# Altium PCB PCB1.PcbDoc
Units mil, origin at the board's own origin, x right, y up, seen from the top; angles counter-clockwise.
Board outline 4318 x 4350 mil, 2 copper layers (Top Layer, Bottom Layer); 0 components, 46 nets, 149 pads, 0 vias.
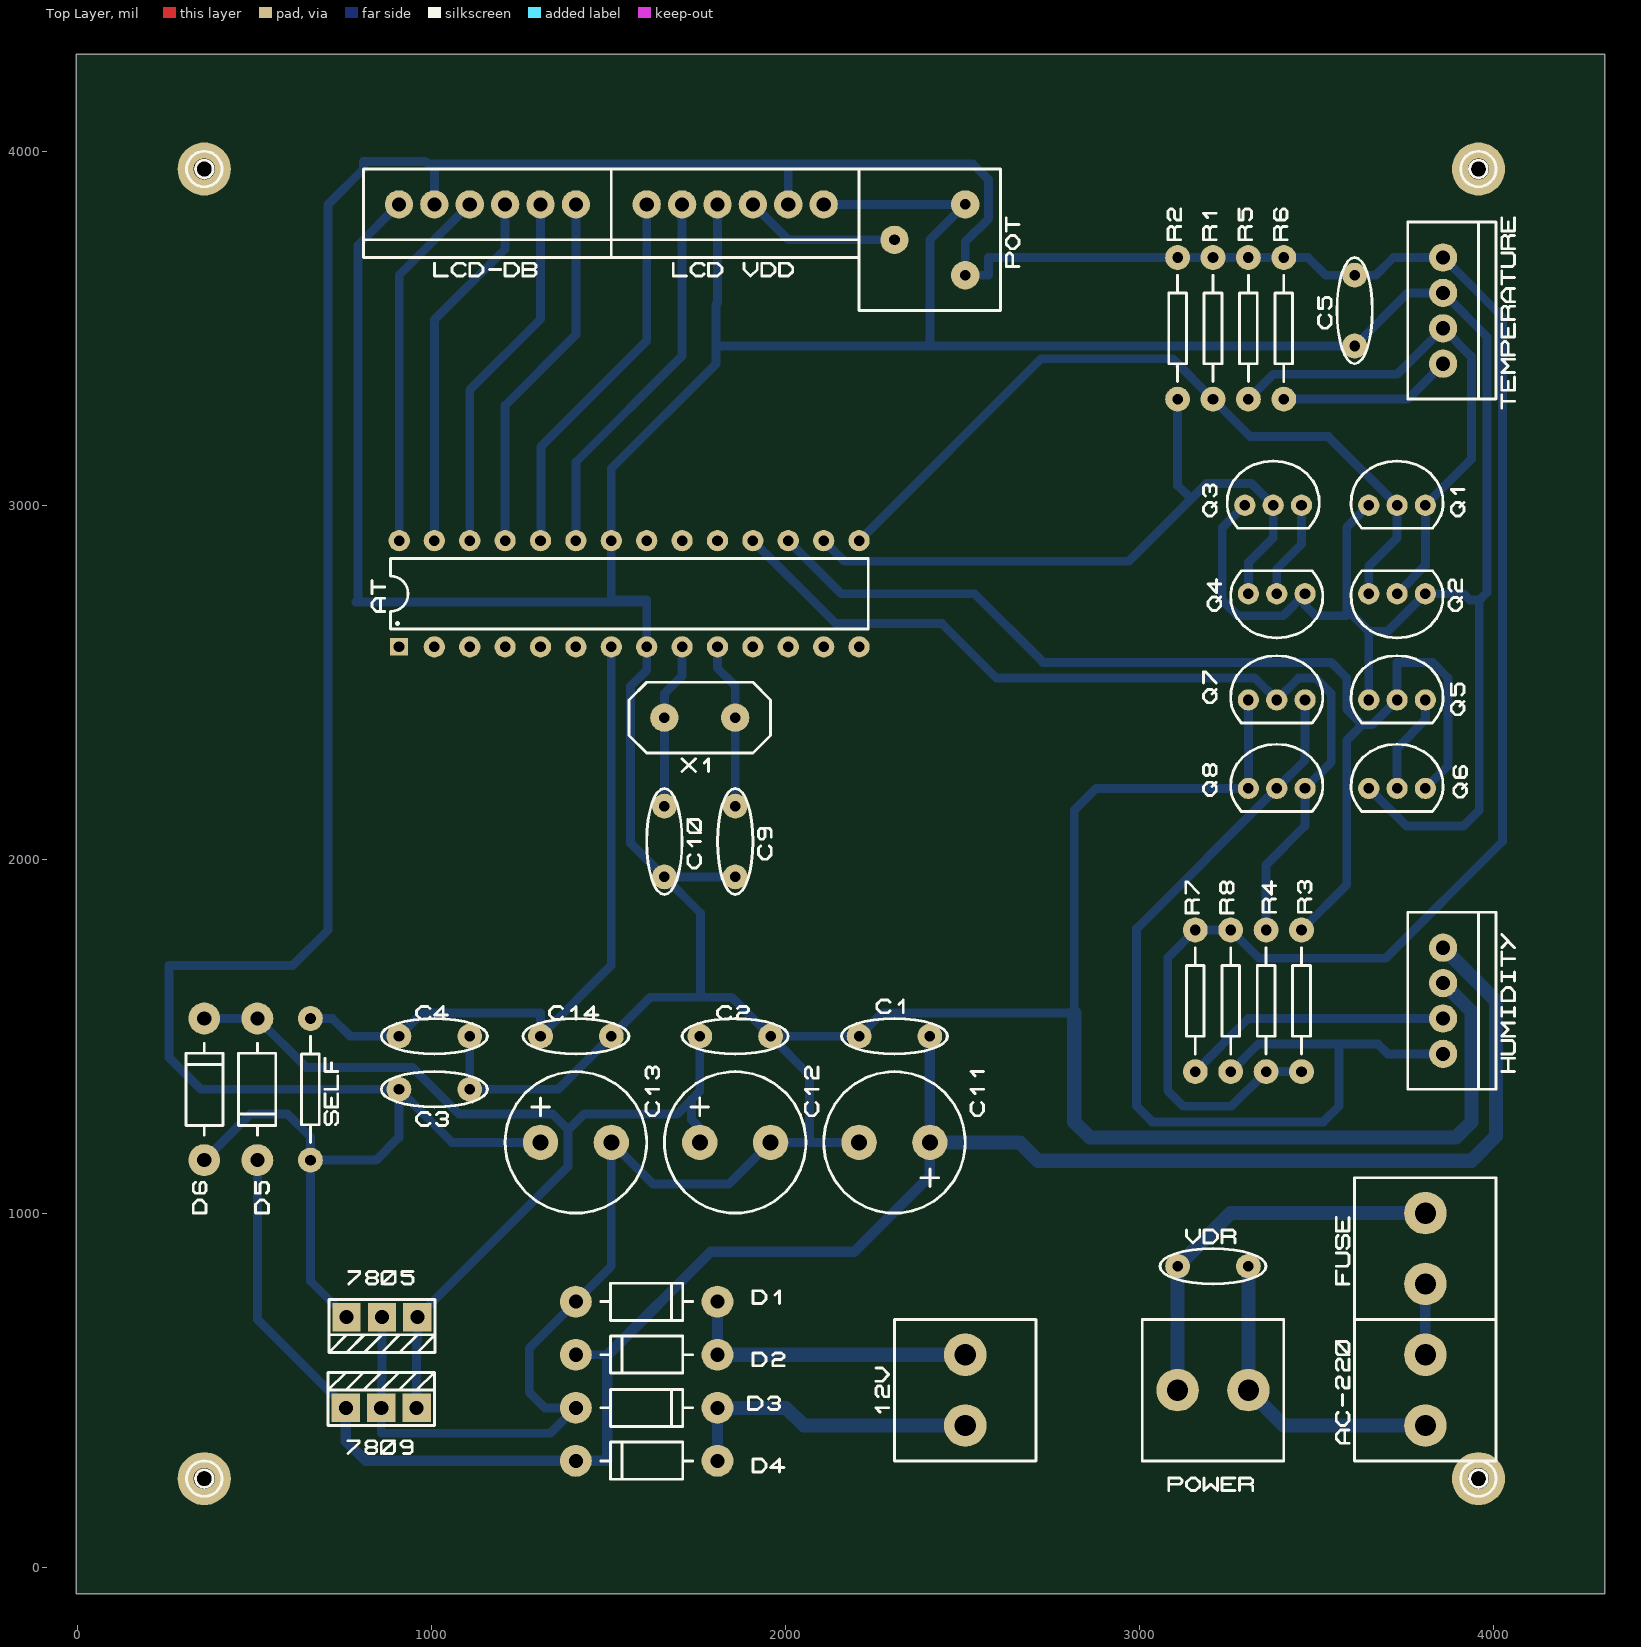
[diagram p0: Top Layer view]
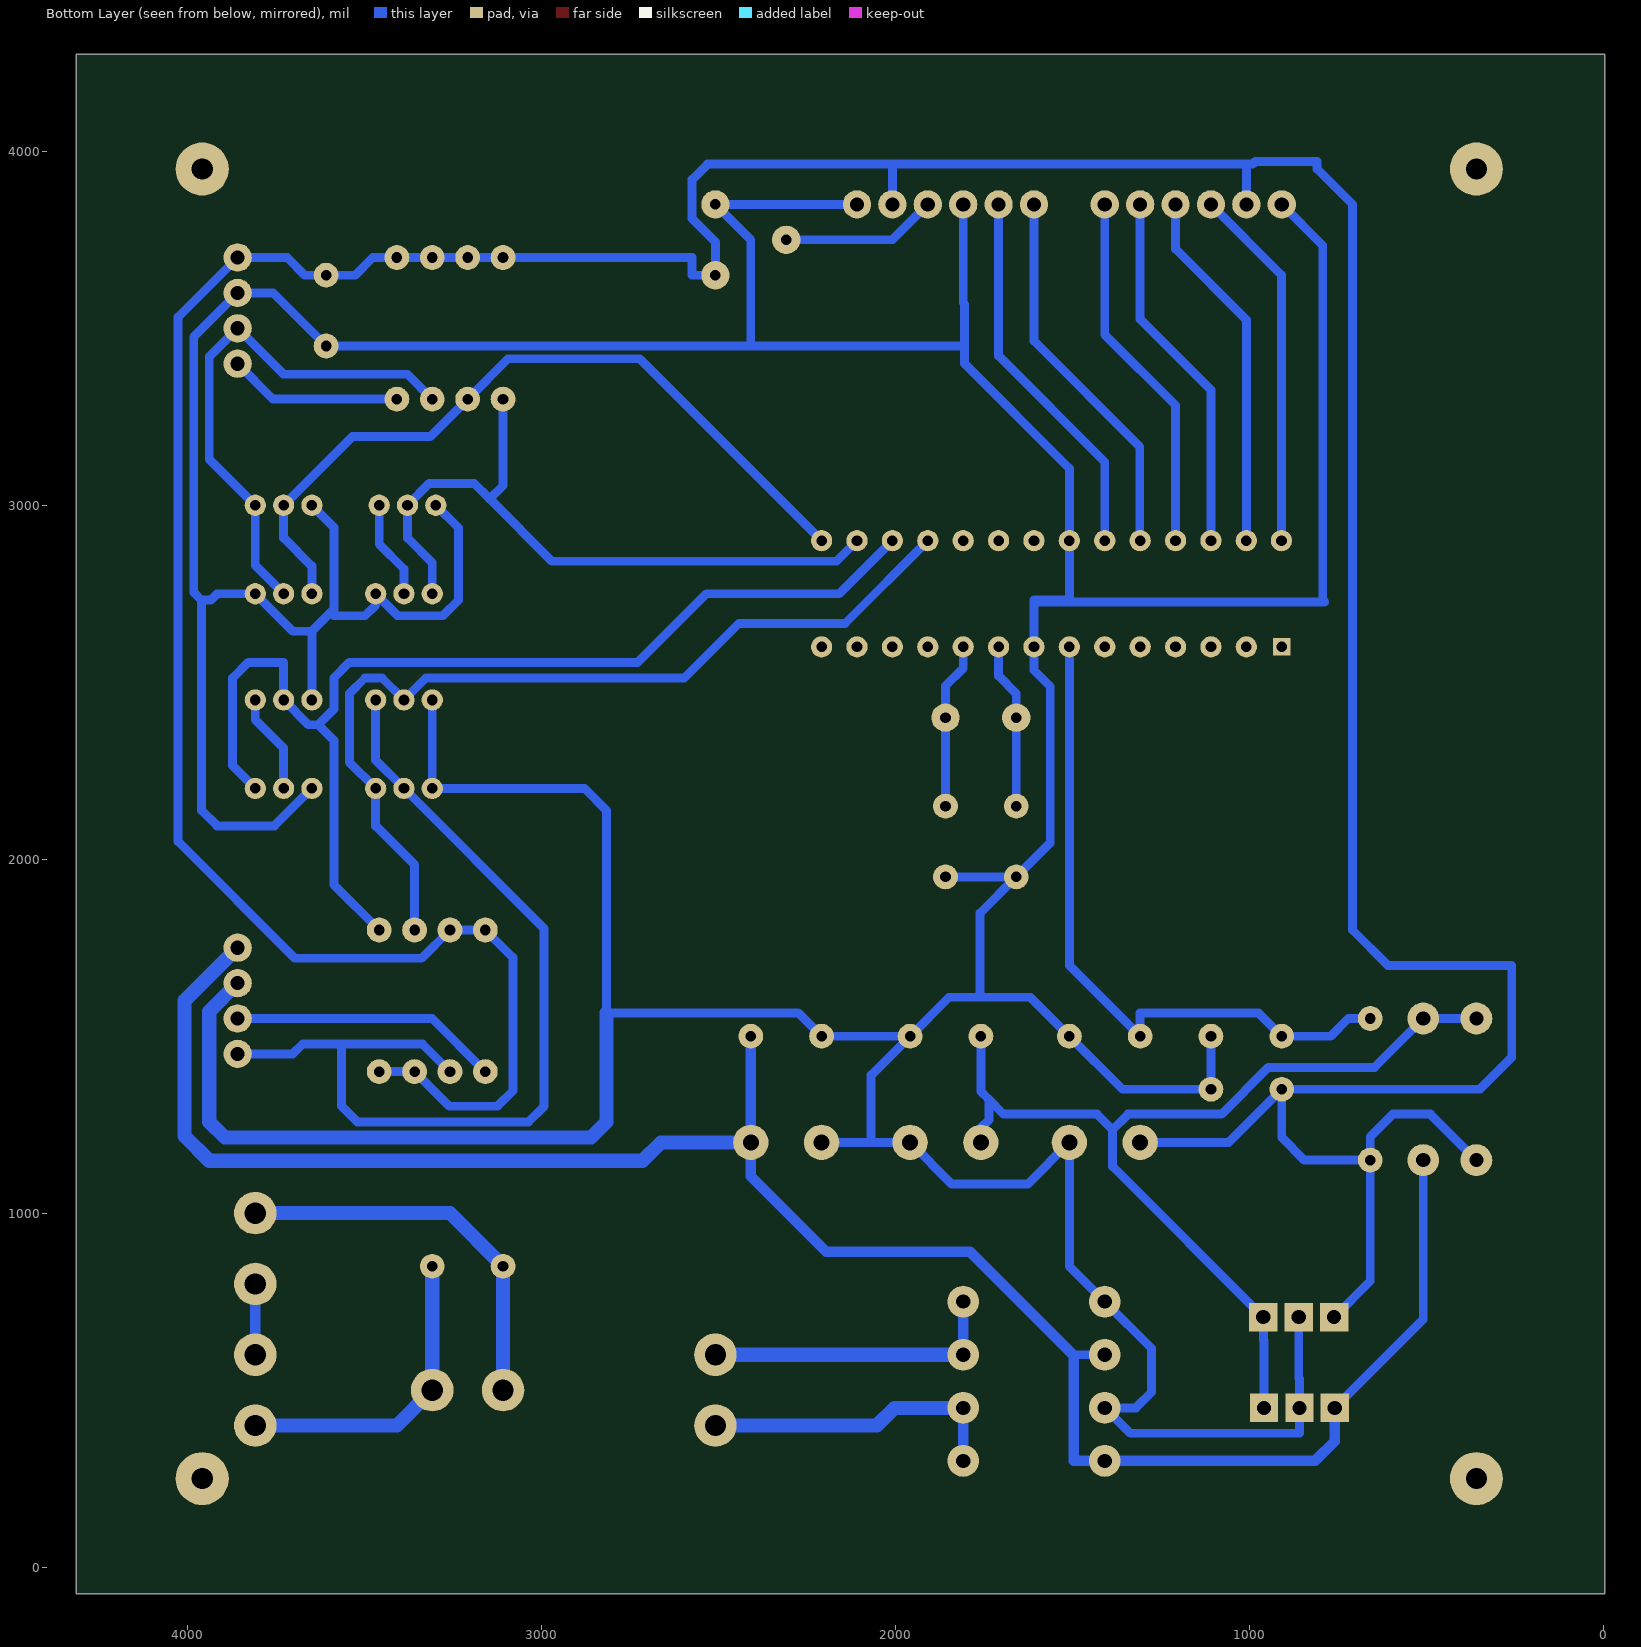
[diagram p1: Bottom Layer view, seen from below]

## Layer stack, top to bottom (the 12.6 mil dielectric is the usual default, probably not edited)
Top Layer: signal copper 1.4
Dielectric: dielectric 12.6, FR-4, Dk 4.8
Bottom Layer: signal copper 1.4

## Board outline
-4,-75 4314,-75 4314,4275 -4,4275

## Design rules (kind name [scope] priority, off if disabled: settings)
Clearance CAM_Clearance_2 [OnLayer('Top Layer')] p1: gap=10
Clearance CAM_Clearance_1 [OnLayer('Bottom Layer')] p2: gap=0
Clearance [All] p3: gap=10
PolygonConnect [All] p1: connectstyle=Relief reliefconductorwidth=10 reliefentries=4 polygonreliefangle="90 Angle"
RoutingVias [All] p1: holewidth=28 width=50 viastyle="Through Hole" minholewidth=28 minwidth=50 maxholewidth=28 maxwidth=50
SilkscreenOverComponentPads [All] p1: minsilkscreentomaskgap=10
SolderMaskExpansion [All] p1: expansion=4
Width CAM_Width_1 [OnLayer('Bottom Layer')] p1: maxlimit=41 minlimit=24 preferedwidth=25
Width [All] p2: maxlimit=10 minlimit=10 preferedwidth=10
27 further rules are at their usual default settings.

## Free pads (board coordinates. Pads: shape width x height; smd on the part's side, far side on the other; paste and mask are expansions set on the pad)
  round 150 hole 60: 1(357.92,250.5) 1(357.92,3950.49) 1(3957.92,250.5) 1(3957.92,3950.49)
  round 90 hole 40: 1(357.92,1150.49) 1(357.92,1550.49) 1(507.92,1150.49) 1(507.92,1550.49) 1(1407.92,300.5) 1(1407.92,450.5) 1(1407.92,600.5) 1(1407.92,750.5) 1(1807.92,300.5) 1(1807.92,450.5) 1(1807.92,600.5) 1(1807.92,750.5)
  round 70 hole 30: 1(657.92,1150.49) 1(657.92,1550.49) 1(907.92,1350.49) 1(907.92,1500.49) 1(1107.92,1350.49) 1(1107.92,1500.49) 1(1307.92,1500.49) 1(1507.92,1500.49) 1(1657.92,1950.49) 1(1657.92,2150.49) 1(1757.92,1500.49) 1(1857.92,1950.49) 1(1857.92,2150.49) 1(1957.92,1500.49) 1(2207.92,1500.49) 1(2407.92,1500.49) 1(3107.92,850.5) 1(3107.92,3300.49) 1(3107.92,3700.49) 1(3157.92,1400.49) 1(3157.92,1800.49) 1(3207.92,3300.49) 1(3207.92,3700.49) 1(3257.92,1400.49) 1(3257.92,1800.49) 1(3307.92,850.5) 1(3307.92,3300.49) 1(3307.92,3700.49) 1(3357.92,1400.49) 1(3357.92,1800.49) 1(3407.92,3300.49) 1(3407.92,3700.49) 1(3457.92,1400.49) 1(3457.92,1800.49) 1(3607.92,3450.49) 1(3607.92,3650.49)
  rect 80x80 hole 40: 1(757.92,450.5) 1(759.92,706.79) 1(857.92,450.5) 1(859.92,706.79) 1(957.92,450.5) 1(959.92,706.79)
  rect 50x50 hole 30: 1(907.92,2600.49)
  round 80 hole 40: 1(907.92,3850.49) 1(1007.92,3850.49) 1(1107.92,3850.49) 1(1207.92,3850.49) 1(1307.92,3850.49) 1(1407.92,3850.49) 1(1607.92,3850.49) 1(1707.92,3850.49) 1(1807.92,3850.49) 1(1907.92,3850.49) 1(2007.92,3850.49) 1(2107.92,3850.49) 1(3857.92,1450.49) 1(3857.92,1550.49) 1(3857.92,1650.49) 1(3857.92,1750.49) 1(3857.92,3400.49) 1(3857.92,3500.49) 1(3857.92,3600.49) 1(3857.92,3700.49)
  round 60 hole 30: 1(908.72,2900.49) 1(1007.92,2600.49) 1(1007.92,2900.49) 1(1107.92,2600.49) 1(1107.92,2900.49) 1(1207.92,2600.49) 1(1207.92,2900.49) 1(1307.92,2600.49) 1(1307.92,2900.49) 1(1407.92,2600.49) 1(1407.92,2900.49) 1(1507.92,2600.49) 1(1507.92,2900.49) 1(1607.92,2600.49) 1(1607.92,2900.49) 1(1707.92,2600.49) 1(1707.92,2900.49) 1(1807.92,2600.49) 1(1807.92,2900.49) 1(1907.92,2600.49) 1(1907.92,2900.49) 1(2007.92,2600.49) 1(2007.92,2900.49) 1(2107.92,2600.49) 1(2107.92,2900.49) 1(2207.92,2600.49) 1(2207.92,2900.49) 1(3297.92,3000.49) 1(3307.92,2200.49) 1(3307.92,2450.49) 1(3307.92,2750.49) 1(3377.92,3000.49) 1(3387.92,2200.49) 1(3387.92,2450.49) 1(3387.92,2750.49) 1(3457.92,3000.49) 1(3467.92,2200.49) 1(3467.92,2450.49) 1(3467.92,2750.49) 1(3647.92,2200.49) 1(3647.92,2450.49) 1(3647.92,2750.49) 1(3647.92,3000.49) 1(3727.92,2200.49) 1(3727.92,2450.49) 1(3727.92,2750.49) 1(3727.92,3000.49) 1(3807.92,2200.49) 1(3807.92,2450.49) 1(3807.92,2750.49) 1(3807.92,3000.49)
  round 100 hole 45: 1(1307.92,1200.49) 1(1507.92,1200.49) 1(1757.92,1200.49) 1(1957.92,1200.49) 1(2207.92,1200.49) 1(2407.92,1200.49)
  round 80 hole 30: 1(1657.92,2400.49) 1(1857.92,2400.49) 1(2307.92,3750.49) 1(2507.92,3650.49) 1(2507.92,3850.49)
  round 120 hole 60: 1(2507.92,400.5) 1(2507.92,600.5) 1(3107.92,500.5) 1(3307.92,500.5) 1(3807.92,400.5) 1(3807.92,600.5) 1(3807.92,800.5) 1(3807.92,1000.5)

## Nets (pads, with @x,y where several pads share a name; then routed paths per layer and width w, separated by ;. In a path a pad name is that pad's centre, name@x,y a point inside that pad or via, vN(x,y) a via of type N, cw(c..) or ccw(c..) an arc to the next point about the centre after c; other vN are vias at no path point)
$Net0: pad.1@907.92,2600.49
$Net1: pad.1@1007.92,2600.49
$Net2: pad.1@1107.92,2600.49
$Net3: pad.1@1207.92,2600.49
$Net4: pad.1@1307.92,2600.49
$Net5: pad.1@1407.92,2600.49
$Net6: pad.1@657.92,1550.49 pad.1@907.92,1500.49 pad.1@1307.92,1500.49 pad.1@1507.92,2600.49 | length 1946.9
  Bottom Layer w25: pad.1@657.92,1550.49 719.92,1550.49 769.92,1500.49 907.92,1500.49 973.92,1566.49 1307.92,1566.49 1307.92,1500.49 1507.92,1700.49 pad.1@1507.92,2600.49
$Net7: pad.1@857.92,450.5 pad.1@859.92,706.79 pad.1@907.92,3850.49 pad.1@1107.92,1350.49 pad.1@1107.92,1500.49 pad.1@1407.92,450.5 pad.1@1407.92,750.5 pad.1@1507.92,1200.49 pad.1@1507.92,1500.49 pad.1@1507.92,2900.49 pad.1@1607.92,2600.49 pad.1@1657.92,1950.49 pad.1@1807.92,3850.49 pad.1@1857.92,1950.49 pad.1@1957.92,1200.49 pad.1@1957.92,1500.49 pad.1@2107.92,3850.49 pad.1@2207.92,1200.49 pad.1@2207.92,1500.49 pad.1@2507.92,3850.49 pad.1@3297.92,3000.49 pad.1@3307.92,2200.49 pad.1@3307.92,2450.49 pad.1@3467.92,2750.49 pad.1@3607.92,3450.49 pad.1@3647.92,2200.49 pad.1@3647.92,2450.49 pad.1@3647.92,3000.49 pad.1@3807.92,2750.49 pad.1@3857.92,1650.49 pad.1@3857.92,3600.49 | length 19607.3
  Bottom Layer w25: pad.1@859.92,706.79 859.92,534.5 857.92,532.5 857.92,450.5 857.92,378.5 1335.92,378.5 1407.92,450.5 1319.92,450.5 1275.92,494.5 1275.92,618.5 1407.92,750.5 1507.92,850.5 1507.92,1200.49 1625.92,1082.49 1839.92,1082.49 1957.92,1200.49 2067.92,1200.49 ; pad.1@907.92,3850.49 791.92,3734.49 791.92,2842.49 791.92,2732.7 787.02,2727.7 1603.22,2727.7 1607.92,2732.49 ; pad.1@1107.92,1500.49 1107.92,1350.49 1357.92,1350.49 1507.92,1500.49 1617.92,1610.49 1759.92,1610.49 ; pad.1@1807.92,3850.49 1807.92,3726.49 1807.92,3572.49 1803.92,3568.49 1803.92,3450.49 ; pad.1@1857.92,1950.49 pad.1@1657.92,1950.49 ; pad.1@2107.92,3850.49 2507.92,3850.49 2407.92,3750.49 2407.92,3450.49 ; pad.1@2207.92,1200.49 2067.92,1200.49 ; pad.1@3297.92,3000.49 3233.92,2936.49 3233.92,2732.49 3277.92,2688.49 3405.92,2688.49 3467.92,2750.49 3467.92,2718.49 3497.92,2688.49 3585.92,2688.49 3585.92,2706.49 ; pad.1@3307.92,2450.49 3307.92,2200.49 2877.92,2200.49 2815.92,2138.49 2815.92,1566.49 2273.92,1566.49 2207.92,1500.49 pad.1@1957.92,1500.49 ; pad.1@3647.92,2200.49 3753.92,2094.49 3915.92,2094.49 3959.92,2138.49 3959.92,2732.49 ; pad.1@3647.92,2450.49 3647.92,2644.49 ; pad.1@3647.92,3000.49 3585.92,2938.49 3585.92,2732.49 3585.92,2706.49 ; 1607.92,2732.49 1507.92,2732.49 1507.92,2900.49 1507.92,3104.49 1803.92,3400.49 1803.92,3450.49 ; 1607.92,2732.49 1607.92,2600.49 1607.92,2534.49 1561.92,2488.49 1561.92,2046.49 pad.1@1657.92,1950.49 ; pad.1@1657.92,1950.49 1759.92,1848.49 1759.92,1610.49 ; 1759.92,1610.49 1847.92,1610.49 pad.1@1957.92,1500.49 ; 1803.92,3450.49 2407.92,3450.49 ; pad.1@1957.92,1500.49 2067.92,1390.49 2067.92,1200.49 ; 2407.92,3450.49 2603.92,3450.49 3607.92,3450.49 3757.92,3600.49 3857.92,3600.49 3981.92,3476.49 3981.92,2754.49 3959.92,2732.49 ; 3585.92,2706.49 3647.92,2644.49 ; 3647.92,2644.49 3701.92,2644.49 3807.92,2750.49 3915.92,2750.49 3933.92,2732.49 3959.92,2732.49
  Bottom Layer w40: 2815.92,1566.49 2815.92,1258.49 2859.92,1214.49 3893.92,1214.49 3937.92,1258.49 3937.92,1570.49 pad.1@3857.92,1650.49
$Net8: pad.1@1657.92,2150.49 pad.1@1657.92,2400.49 pad.1@1707.92,2600.49 | length 470.7
  Bottom Layer w25: pad.1@1657.92,2150.49 1657.92,2400.49 1657.92,2468.49 1707.92,2518.49 pad.1@1707.92,2600.49
$Net9: pad.1@1807.92,2600.49 pad.1@1857.92,2150.49 pad.1@1857.92,2400.49 | length 470.7
  Bottom Layer w25: pad.1@1807.92,2600.49 1807.92,2540.49 1857.92,2490.49 1857.92,2400.49 pad.1@1857.92,2150.49
$Net10: pad.1@1907.92,2600.49
$Net11: pad.1@2007.92,2600.49
$Net12: pad.1@2107.92,2600.49
$Net13: pad.1@2207.92,2600.49
$Net14: pad.1@2207.92,2900.49 pad.1@3207.92,3300.49 pad.1@3647.92,2750.49 pad.1@3727.92,3000.49 | length 2187.5
  Bottom Layer w25: pad.1@2207.92,2900.49 2721.92,3414.49 3093.92,3414.49 3207.92,3300.49 3313.92,3194.49 3533.92,3194.49 3727.92,3000.49 3727.92,2908.49 3647.92,2828.49 pad.1@3647.92,2750.49
$Net15: pad.1@2107.92,2900.49 pad.1@3107.92,3300.49 pad.1@3307.92,2750.49 pad.1@3377.92,3000.49 | length 1987.6
  Bottom Layer w25: pad.1@2107.92,2900.49 2165.92,2842.49 2969.92,2842.49 3145.92,3018.49 ; pad.1@3107.92,3300.49 3107.92,3056.49 3145.92,3018.49 ; pad.1@3307.92,2750.49 3307.92,2838.49 3377.92,2908.49 3377.92,3000.49 3315.92,3062.49 3189.92,3062.49 3145.92,3018.49
$Net16: pad.1@2007.92,2900.49 pad.1@3457.92,1800.49 pad.1@3727.92,2450.49 pad.1@3807.92,2200.49 | length 3273.9
  Bottom Layer w25: pad.1@2007.92,2900.49 2157.92,2750.49 2533.92,2750.49 2727.92,2556.49 3541.92,2556.49 3585.92,2512.49 3585.92,2424.49 3629.92,2380.49 ; pad.1@3457.92,1800.49 3585.92,1928.49 3585.92,2336.49 3629.92,2380.49 ; pad.1@3807.92,2200.49 3871.92,2264.49 3871.92,2512.49 3827.92,2556.49 3727.92,2556.49 3727.92,2450.49 3657.92,2380.49 3629.92,2380.49
$Net17: pad.1@1907.92,2900.49 pad.1@3357.92,1800.49 pad.1@3387.92,2450.49 pad.1@3467.92,2200.49 | length 2608.5
  Bottom Layer w25: pad.1@1907.92,2900.49 2141.92,2666.49 2441.92,2666.49 2595.92,2512.49 3325.92,2512.49 3387.92,2450.49 3449.92,2512.49 3497.92,2512.49 3541.92,2468.49 3541.92,2274.49 3467.92,2200.49 3467.92,2094.49 3357.92,1984.49 pad.1@3357.92,1800.49
$Net18: pad.1@1807.92,2900.49
$Net19: pad.1@1707.92,2900.49
$Net20: pad.1@1607.92,2900.49
$Net21: pad.1@1407.92,2900.49 pad.1@1707.92,3850.49 | length 1074.3
  Bottom Layer w25: pad.1@1407.92,2900.49 1408.12,2900.59 1408.12,3122.89 1707.92,3422.7 1707.92,3450.49 pad.1@1707.92,3850.49
$Net22: pad.1@1307.92,2900.49 pad.1@1607.92,3850.49 | length 1074.3
  Bottom Layer w25: pad.1@1307.92,2900.49 1309.02,2901.49 1309.02,3165.99 1607.92,3464.89 1607.92,3550.49 pad.1@1607.92,3850.49
$Net23: pad.1@1207.92,2900.49 pad.1@1407.92,3850.49 | length 1032.8
  Bottom Layer w25: pad.1@1207.92,2900.49 1207.92,3282.49 1407.92,3482.49 pad.1@1407.92,3850.49
$Net24: pad.1@1107.92,2900.49 pad.1@1307.92,3850.49 | length 1032.8
  Bottom Layer w25: pad.1@1107.92,2900.49 1107.92,3326.49 1307.92,3526.49 pad.1@1307.92,3850.49
$Net25: pad.1@1007.92,2900.49 pad.1@1207.92,3850.49 | length 1032.8
  Bottom Layer w25: pad.1@1007.92,2900.49 1007.92,3524.49 1207.92,3724.49 pad.1@1207.92,3850.49
$Net26: pad.1@908.72,2900.49 pad.1@1107.92,3850.49 | length 1032.5
  Bottom Layer w25: pad.1@908.72,2900.49 908.72,3651.2 pad.1@1107.92,3850.49
$Net27: pad.1@3307.92,3300.49 pad.1@3727.92,2750.49 pad.1@3807.92,3000.49 pad.1@3857.92,3500.49 | length 1503
  Bottom Layer w25: pad.1@3307.92,3300.49 3377.92,3370.49 3727.92,3370.49 3857.92,3500.49 3937.92,3420.49 3937.92,3130.49 3807.92,3000.49 3807.92,2830.49 pad.1@3727.92,2750.49
$Net28: pad.1@3387.92,2750.49 pad.1@3457.92,3000.49 | length 279
  Bottom Layer w25: pad.1@3387.92,2750.49 3387.92,2820.49 3457.92,2890.49 pad.1@3457.92,3000.49
$Net29: pad.1@3727.92,2200.49 pad.1@3807.92,2450.49 | length 283.1
  Bottom Layer w25: pad.1@3727.92,2200.49 3727.92,2314.49 3807.92,2394.49 pad.1@3807.92,2450.49
$Net30: pad.1@3257.92,1400.49 pad.1@3387.92,2200.49 pad.1@3467.92,2450.49 pad.1@3857.92,1450.49 | length 2773.5
  Bottom Layer w25: pad.1@3257.92,1400.49 3335.92,1478.49 3519.92,1478.49 3563.92,1478.49 ; pad.1@3467.92,2450.49 3467.92,2280.49 3387.92,2200.49 2991.92,1804.49 2991.92,1302.49 3035.92,1258.49 3519.92,1258.49 3563.92,1302.49 3563.92,1434.49 3563.92,1478.49 ; pad.1@3857.92,1450.49 3701.92,1450.49 3673.92,1478.49 3563.92,1478.49
$Net31: pad.1@357.92,1150.49 pad.1@657.92,1150.49 pad.1@759.92,706.79 pad.1@907.92,1350.49 pad.1@1007.92,3850.49 pad.1@1307.92,1200.49 pad.1@2007.92,3850.49 pad.1@2507.92,3650.49 pad.1@3107.92,3700.49 pad.1@3157.92,1800.49 pad.1@3207.92,3700.49 pad.1@3257.92,1800.49 pad.1@3307.92,3700.49 pad.1@3357.92,1400.49 pad.1@3407.92,3700.49 pad.1@3457.92,1400.49 pad.1@3607.92,3650.49 pad.1@3857.92,3700.49 | length 12893.2
  Bottom Layer w25: pad.1@357.92,1150.49 487.92,1280.49 593.92,1280.49 657.92,1216.49 pad.1@657.92,1150.49 ; pad.1@759.92,706.79 657.92,808.79 pad.1@657.92,1150.49 ; pad.1@1007.92,3850.49 1007.92,3964.49 ; pad.1@1307.92,1200.49 1057.92,1200.49 pad.1@907.92,1350.49 ; pad.1@2007.92,3850.49 2007.92,3964.49 ; pad.1@3457.92,1400.49 3357.92,1400.49 3259.92,1302.49 3123.92,1302.49 3079.92,1346.49 3079.92,1722.49 3157.92,1800.49 3257.92,1800.49 3337.92,1720.49 3695.92,1720.49 4025.92,2050.49 4025.92,3532.49 3857.92,3700.49 3717.92,3700.49 3667.92,3650.49 3607.92,3650.49 3525.92,3650.49 3475.92,3700.49 3407.92,3700.49 3307.92,3700.49 3207.92,3700.49 3107.92,3700.49 2573.92,3700.49 2573.92,3650.49 2507.92,3650.49 2507.92,3744.49 2573.92,3810.49 2573.92,3920.49 2529.92,3964.49 2067.92,3964.49 2007.92,3964.49 ; pad.1@657.92,1150.49 843.92,1150.49 907.92,1214.49 pad.1@907.92,1350.49 ; pad.1@907.92,1350.49 347.92,1350.49 257.92,1440.49 257.92,1700.49 607.92,1700.49 707.92,1800.49 707.92,3850.49 807.92,3950.49 807.92,3971.99 982.42,3971.99 989.92,3964.49 1007.92,3964.49 ; 1007.92,3964.49 2007.92,3964.49
$Net32: pad.1@3407.92,3300.49 pad.1@3857.92,3400.49 | length 491.4
  Bottom Layer w25: pad.1@3407.92,3300.49 3463.42,3300.49 3757.92,3300.49 pad.1@3857.92,3400.49
$Net33: pad.1@3157.92,1400.49 pad.1@3857.92,1550.49 | length 762.1
  Bottom Layer w25: pad.1@3157.92,1400.49 3307.92,1550.49 3585.92,1550.49 pad.1@3857.92,1550.49
$Net34: pad.1@507.92,1150.49 pad.1@757.92,450.5 pad.1@1407.92,300.5 pad.1@1407.92,600.5 pad.1@2407.92,1200.49 pad.1@2407.92,1500.49 pad.1@3857.92,1750.49 | length 5807.8
  Bottom Layer w25: pad.1@507.92,1150.49 507.92,700.5 pad.1@757.92,450.5 ; pad.1@1407.92,600.5 1493.92,600.5 1495.92,598.5
  Bottom Layer w30: pad.1@757.92,450.5 757.92,356.5 813.92,300.5 1407.92,300.5 1495.92,300.5 1495.92,598.5 1788.72,891.29 2194.72,891.29 2407.92,1104.49 2407.92,1200.49 pad.1@2407.92,1500.49
  Bottom Layer w40: pad.1@2407.92,1200.49 2661.92,1200.49 2713.92,1148.49 3937.92,1148.49 4007.92,1218.49 4007.92,1600.49 pad.1@3857.92,1750.49
$Net35: pad.1@357.92,1550.49 pad.1@507.92,1550.49 pad.1@957.92,450.5 pad.1@959.92,706.79 pad.1@1757.92,1200.49 pad.1@1757.92,1500.49 | length 2824.5
  Bottom Layer w25: pad.1@357.92,1550.49 507.92,1550.49 645.92,1412.49 945.92,1412.49 1077.92,1280.49 1341.92,1280.49 1385.92,1236.49 ; pad.1@957.92,450.5 957.92,640.6 959.92,642.5 959.92,706.79 1385.92,1132.8 1385.92,1236.49 ; pad.1@1757.92,1200.49 1757.92,1241.39 1734.82,1264.6 1734.82,1321.3 ; pad.1@1757.92,1500.49 1757.92,1344.49 1737.92,1324.49 1734.82,1321.3 ; 1385.92,1236.49 1429.92,1280.49 1693.92,1280.49 1734.82,1321.3
$Net36: pad.1@3107.92,500.5 pad.1@3107.92,850.5 pad.1@3807.92,1000.5 | length 1112.1
  Bottom Layer w40: pad.1@3107.92,500.5 3107.92,850.5 3257.92,1000.5 pad.1@3807.92,1000.5
$Net37: pad.1@3307.92,500.5 pad.1@3307.92,850.5 pad.1@3807.92,400.5 | length 891.4
  Bottom Layer w40: pad.1@3307.92,850.5 3307.92,500.5 3407.92,400.5 pad.1@3807.92,400.5
$Net38: pad.1@1907.92,3850.49 pad.1@2307.92,3750.49 | length 441.4
  Bottom Layer w25: pad.1@1907.92,3850.49 2007.92,3750.49 pad.1@2307.92,3750.49
$Net39: pad.1@1807.92,600.5 pad.1@1807.92,750.5 pad.1@2507.92,600.5 | length 850
  Bottom Layer w30: pad.1@1807.92,600.5 pad.1@1807.92,750.5
  Bottom Layer w40: pad.1@1807.92,600.5 pad.1@2507.92,600.5
$Net40: pad.1@1807.92,300.5 pad.1@1807.92,450.5 pad.1@2507.92,400.5 | length 870.7
  Bottom Layer w30: pad.1@1807.92,300.5 pad.1@1807.92,450.5
  Bottom Layer w40: pad.1@1807.92,450.5 2001.92,450.5 2051.92,400.5 pad.1@2507.92,400.5
$Net41: pad.1@3807.92,600.5 pad.1@3807.92,800.5 | length 200
  Bottom Layer w30: pad.1@3807.92,600.5 pad.1@3807.92,800.5
$Net42: pad.1@3957.92,3950.49
$Net43: pad.1@357.92,3950.49
$Net44: pad.1@357.92,250.5
$Net45: pad.1@3957.92,250.5

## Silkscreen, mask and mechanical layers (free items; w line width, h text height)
Top Overlay:
  drawing of 2061 lines, arcs and shapes, not listed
